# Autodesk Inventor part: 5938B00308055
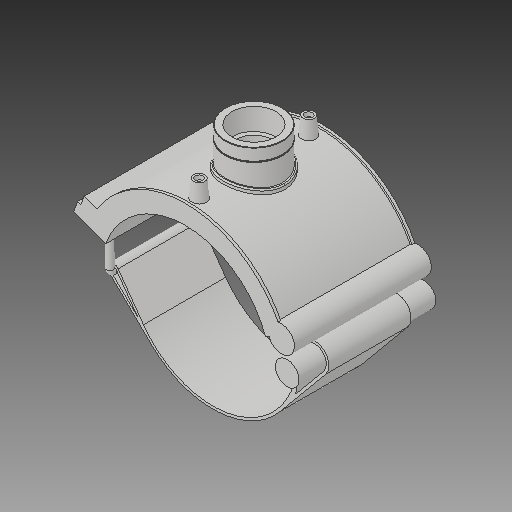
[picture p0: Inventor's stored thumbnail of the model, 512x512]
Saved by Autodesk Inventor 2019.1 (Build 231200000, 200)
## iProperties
Created: 2017-07
Part Number: 5938B00308055
Material: Generic
Description: PLASSON TRANSITION SADDLE 8''IPS x 2"NPT
Document SubType Name: Modeling
Designer: KIM
Density: 1 g/cm^3
Appearance: Default
Author: KIM
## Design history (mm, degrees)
derived "5938B.ipt"
feature "Solid1::5938B.ipt"
tag "TaggingFeature1"
body "Solid1"
other parameters: "d0" = 218.7, "d1" = 262.44, "d2" = 449.58, "d3" = 54.675, "d4" = 176.022, "d5" = 0, "d40" = 136.4688, "d41" = 79.3184, "d43" = 0, "d45" = 0, "d47" = 177.956, "d48" = 73.6528, "d50" = 0, "d78" = 153.22, "d79" = 15, "d80" = 70.4088, "d82" = 5 deg, "d84" = 4, "d85" = 14, "d86" = 0, "d87" = 3, "d88" = 0, "d96" = 267.6888, "d97" = 3.52044, "d98" = 0, "d102" = 1.69968, "d103" = 56.656, "d104" = 28.0416, "d105" = 0, "d106" = 45.3248, "d108" = 0, "d109" = -15.57867, "d111" = 0.5, "d112" = 0.5, "d113" = 0, "d114" = 0.5, "d117" = 0.56656, "d120" = 140 deg, "d121" = 24.228, "d122" = 20 deg, "d123" = 1049.76, "d124" = 157.464, "d126" = 0, "d143" = 225.261, "d145" = 33.64615, "d149" = 3.2805, "d150" = 37.01077, "d153" = 176.022, "d154" = 0, "d156" = 131.22, "d157" = 160 deg, "d159" = 8.748, "d161" = 3.2805, "d162" = 105.6132, "d163" = 0, "d164" = 109.35, "d167" = 21.87, "d168" = 128.01951, "d170" = 3.2805, "d172" = 0, "d173" = 1, "d175" = 109.35, "d176" = 20 deg, "d177" = 15.309, "d178" = 43.74, "d180" = 0, "d183" = 17.496, "d184" = 12.2472, "d185" = 57.20715, "d186" = 57.20715, "d187" = 131.22, "d188" = 13.122, "d189" = 15.309, "d190" = 0, "d191" = 157.464, "d193" = 8.748, "d194" = 4.48335, "d195" = 90 deg, "d197" = 0, "d199" = 0, "d_" = 218.7, "B_" = 179.832, "H_" = 46.736, "L_" = 176.022, "d_t" = 6, "G_" = 56.656, "d148" = 3.2805, "d160" = 3.2805, "d169" = 3.2805, "d192" = 8.748
